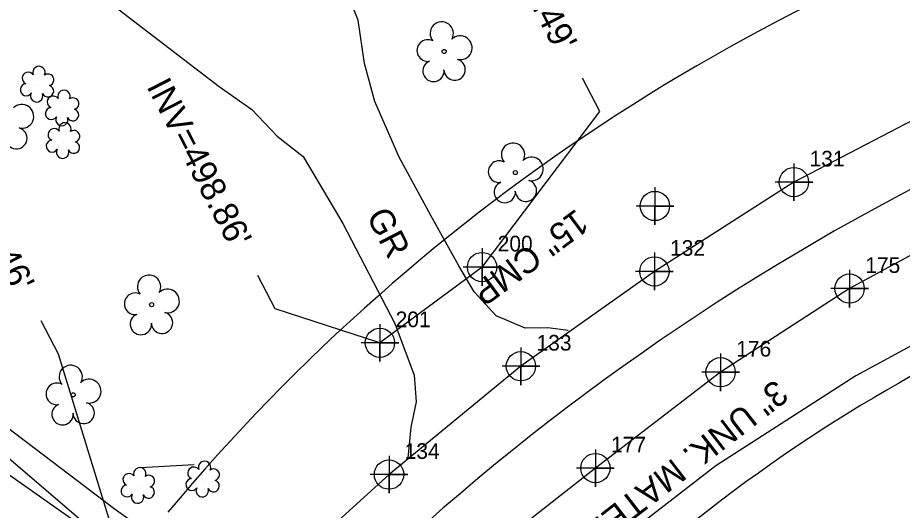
# Model space of a CAD drawing. Extents: x 1534145 to 1537876, y 509021 to 513201.
# Drawn here: x 1536471.7 to 1536612.8, y 511366.8 to 511445.5 of the extents above; entities that cross this region are included whole.
import ezdxf

# ---------------------------------------------------------------- set-up
doc = ezdxf.new("R2010")
doc.units = 0
for name, color, linetype in [('Default Symbol CELL', 7, 'Continuous'), ('Exist Horizontal Alignment', 7, 'Continuous'), ('Exist Other Culture Billboard Cableway', 7, 'Continuous'), ('Exist Right of Way Line', 7, 'Continuous'), ('Exist Roads EOP', 7, 'Continuous'), ('Exist Roads EOP Cogo Number', 7, 'Continuous'), ('Exist Roads EOP Cogo Point CELL', 7, 'Continuous'), ('Exist Roads Soil', 7, 'Continuous'), ('Exist Roads Soil Text', 7, 'Continuous'), ('Exist Structure Minor Pipes CMP 15 Inch', 7, 'Continuous'), ('Exist Structure Minor Pipes CMP 15 Inch Cogo Number', 7, 'Continuous'), ('Exist Structure Minor Pipes CMP 15 Inch Cogo Point CELL', 7, 'Continuous'), ('Exist Structure Minor Pipes CMP 15 Inch Invert', 7, 'Continuous'), ('Exist Structure Minor Pipes CMP 15 Inch Text', 7, 'Continuous'), ('Exist Structure Minor Pipes CMP 18 Inch Invert', 7, 'Continuous'), ('Exist Utilities Telephone UG FO SUE', 7, 'Continuous'), ('Exist Utilities TV UG Cable', 7, 'Continuous'), ('Exist Utilities Water UG Line SUE', 7, 'Continuous'), ('Exist Utilities Water UG Line SUE Text', 7, 'Continuous'), ('Exist Vegetation Shrub CELL', 7, 'Continuous'), ('Exist Vegetation Tree CELL', 7, 'Continuous')]:
    doc.layers.add(name, color=color, linetype=linetype)

msp = doc.modelspace()

# ---------------------------------------------------------------- linework, layer by layer
at = {"layer": 'Default Symbol CELL'}
msp.add_lwpolyline([(1536573.37, 511418.41), (1536573.37, 511412.41), (1536573.37, 511415.41), (1536576.37, 511415.41), (1536570.37, 511415.41)], dxfattribs=at)
msp.add_circle((1536573.37, 511415.41), 2.34, dxfattribs=at)
at = {"layer": 'Exist Horizontal Alignment'}
msp.add_arc((1536795.22, 511072.63), 390, 105.6865, 140.1365, dxfattribs=at)
at = {"layer": 'Exist Other Culture Billboard Cableway'}
msp.add_lwpolyline([(1536491.3, 511373.67), (1536499.85, 511374.11)], dxfattribs=at)
at = {"layer": 'Exist Right of Way Line'}
msp.add_lwpolyline([(1536145.81, 511737.79), (1536209.6, 511636.11), (1536268.44, 511561.44), (1536375.73, 511456.33), (1536489.24, 511358.86)], dxfattribs=at)
for radius in [319.6, 259.6]:
    msp.add_arc((1536740.96, 511161.67), radius, 105.6865, 140.1365, dxfattribs=at)
at = {"layer": 'Exist Roads EOP'}
for points in [[(1536631.58, 511437.38), (1536631.26, 511437.24), (1536618.41, 511431.15), (1536595.54, 511419.22), (1536573.28, 511404.96), (1536551.98, 511389.82), (1536530.94, 511372.53), (1536511.9, 511355.24), (1536502.63, 511347.19), (1536496.64, 511344.02), (1536490.92, 511343.71), (1536482.45, 511344.56), (1536475.44, 511348.14), (1536453.49, 511366.6), (1536410.8, 511403.51), (1536369.08, 511439.8), (1536328.72, 511476.49)], [(1536643.71, 511422.19), (1536639.39, 511420.35), (1536626.28, 511414.11), (1536604.43, 511402.22), (1536583.84, 511388.86), (1536563.87, 511373.55), (1536543.15, 511357.26), (1536525.59, 511342.05), (1536518.95, 511333.47), (1536516.92, 511324.68), (1536516.34, 511315.32), (1536522.83, 511308.58), (1536535.62, 511298.19), (1536578.33, 511263.58), (1536620.78, 511229.16), (1536664.52, 511193.98), (1536707, 511159.44), (1536743.27, 511128.84)]]:
    msp.add_lwpolyline(points, dxfattribs=at)
at = {"layer": 'Exist Roads EOP Cogo Point CELL'}
for points in [[(1536595.54, 511422.22), (1536595.54, 511416.22), (1536595.54, 511419.22), (1536598.54, 511419.22), (1536592.54, 511419.22)], [(1536573.28, 511407.96), (1536573.28, 511401.96), (1536573.28, 511404.96), (1536576.28, 511404.96), (1536570.28, 511404.96)], [(1536604.43, 511405.22), (1536604.43, 511399.22), (1536604.43, 511402.22), (1536607.43, 511402.22), (1536601.43, 511402.22)], [(1536551.98, 511392.82), (1536551.98, 511386.82), (1536551.98, 511389.82), (1536554.98, 511389.82), (1536548.98, 511389.82)], [(1536583.84, 511391.86), (1536583.84, 511385.86), (1536583.84, 511388.86), (1536586.84, 511388.86), (1536580.84, 511388.86)], [(1536563.87, 511376.55), (1536563.87, 511370.55), (1536563.87, 511373.55), (1536566.87, 511373.55), (1536560.87, 511373.55)], [(1536530.94, 511375.53), (1536530.94, 511369.53), (1536530.94, 511372.53), (1536533.94, 511372.53), (1536527.94, 511372.53)]]:
    msp.add_lwpolyline(points, dxfattribs=at)
for centre in [(1536595.54, 511419.22), (1536573.28, 511404.96), (1536604.43, 511402.22), (1536551.98, 511389.82), (1536583.84, 511388.86), (1536563.87, 511373.55), (1536530.94, 511372.53)]:
    msp.add_circle(centre, 2.34, dxfattribs=at)
at = {"layer": 'Exist Roads Soil'}
for points in [[(1536559.52, 511395.55), (1536556.28, 511395.95), (1536552.65, 511395.88), (1536548.04, 511397.86), (1536544.5, 511401.73), (1536542.08, 511405.87), (1536537.59, 511413.88), (1536532.56, 511423.21), (1536528.7, 511432.08), (1536527.05, 511438.17), (1536526.04, 511445.06), (1536516.68, 511468.36), (1536514.31, 511473.66)], [(1536479.05, 511454.45), (1536484.68, 511449.25), (1536503.86, 511434.49), (1536509.05, 511430.81), (1536513.11, 511426.58), (1536517.23, 511423.29), (1536523.59, 511412.59), (1536531.84, 511396.62), (1536534.97, 511388.37), (1536535.29, 511384.16)], [(1536535.29, 511384.16), (1536534.4, 511380.09)], [(1536534.4, 511380.09), (1536533.96, 511375.13)]]:
    msp.add_lwpolyline(points, dxfattribs=at)
at = {"layer": 'Exist Structure Minor Pipes CMP 15 Inch'}
msp.add_line((1536545.78, 511405.66), (1536529.49, 511393.56), dxfattribs=at)
at = {"layer": 'Exist Structure Minor Pipes CMP 15 Inch Cogo Point CELL'}
for points in [[(1536545.78, 511408.66), (1536545.78, 511402.66), (1536545.78, 511405.66), (1536548.78, 511405.66), (1536542.78, 511405.66)], [(1536529.49, 511396.56), (1536529.49, 511390.56), (1536529.49, 511393.56), (1536532.49, 511393.56), (1536526.49, 511393.56)]]:
    msp.add_lwpolyline(points, dxfattribs=at)
for centre in [(1536545.78, 511405.66), (1536529.49, 511393.56)]:
    msp.add_circle(centre, 2.34, dxfattribs=at)
at = {"layer": 'Exist Structure Minor Pipes CMP 15 Inch Invert'}
for points in [[(1536545.78, 511405.66), (1536564.56, 511430.51), (1536561.81, 511435.84)], [(1536529.49, 511393.56), (1536512.76, 511398.98), (1536510.01, 511404.31)]]:
    msp.add_lwpolyline(points, dxfattribs=at)
at = {"layer": 'Exist Structure Minor Pipes CMP 18 Inch Invert'}
msp.add_lwpolyline([(1536489.17, 511356.02), (1536478.18, 511391.73), (1536475.42, 511397.07)], dxfattribs=at)
at = {"layer": 'Exist Utilities Telephone UG FO SUE'}
for p, q in [((1536461.86, 511386.19), (1536487.09, 511367.1)), ((1536487.09, 511367.1), (1536505.96, 511353.75))]:
    msp.add_line(p, q, dxfattribs=at)
at = {"layer": 'Exist Utilities TV UG Cable'}
msp.add_line((1536457.6, 511381.47), (1536483.03, 511363.56), dxfattribs=at)
at = {"layer": 'Exist Utilities Water UG Line SUE'}
for p, q in [((1536626.76, 511399.92), (1536605.41, 511388.3)), ((1536605.41, 511388.3), (1536583.08, 511373.94)), ((1536583.08, 511373.94), (1536564.85, 511359.84))]:
    msp.add_line(p, q, dxfattribs=at)
at = {"layer": 'Exist Vegetation Shrub CELL'}
for p, q in [((1536474.86, 511434.69), (1536474.86, 511434.69)), ((1536478.86, 511430.88), (1536478.86, 511430.88)), ((1536479, 511425.68), (1536479, 511425.68)), ((1536490.94, 511370.61), (1536490.94, 511370.61)), ((1536501.28, 511371.63), (1536501.28, 511371.63))]:
    msp.add_line(p, q, dxfattribs=at)
for centre, radius, start, end in [((1536473.38, 511435.81), 0.968, 35.8908, 245.4216), ((1536475.09, 511436.73), 0.99, 334.8391, 200.4717), ((1536476.53, 511435.56), 0.929, 284.4567, 126.0861), ((1536473.06, 511433.98), 0.955, 95.1099, 327.9534), ((1536476.5, 511433.76), 0.937, 204.9913, 73.4601), ((1536479.08, 511432.92), 0.99, 334.8391, 200.4717), ((1536474.73, 511433), 0.984, 151.2797, 21.387), ((1536477.37, 511432), 0.968, 35.8908, 245.4216), ((1536480.53, 511431.75), 0.929, 284.4567, 126.0861), ((1536477.06, 511430.17), 0.955, 95.1099, 327.9534), ((1536478.73, 511429.19), 0.984, 151.2797, 21.387), ((1536480.49, 511429.95), 0.937, 204.9913, 73.4601), ((1536479.23, 511427.72), 0.99, 334.8391, 200.4717), ((1536477.52, 511426.81), 0.968, 35.8908, 245.4216), ((1536480.67, 511426.55), 0.929, 284.4567, 126.0861), ((1536477.2, 511424.98), 0.955, 95.1099, 327.9534), ((1536480.64, 511424.75), 0.937, 204.9913, 73.4601), ((1536478.87, 511424), 0.984, 151.2797, 21.387), ((1536501.51, 511373.67), 0.99, 334.8391, 200.4717), ((1536491.17, 511372.65), 0.99, 334.8391, 200.4717), ((1536499.8, 511372.75), 0.968, 35.8908, 245.4216), ((1536502.95, 511372.5), 0.929, 284.4567, 126.0861), ((1536489.45, 511371.73), 0.968, 35.8908, 245.4216), ((1536492.61, 511371.48), 0.929, 284.4567, 126.0861), ((1536499.48, 511370.92), 0.955, 95.1099, 327.9534), ((1536489.14, 511369.9), 0.955, 95.1099, 327.9534), ((1536492.57, 511369.68), 0.937, 204.9913, 73.4601), ((1536501.15, 511369.94), 0.984, 151.2797, 21.387), ((1536502.92, 511370.7), 0.937, 204.9913, 73.4601), ((1536490.81, 511368.92), 0.984, 151.2797, 21.387)]:
    msp.add_arc(centre, radius, start, end, dxfattribs=at)
at = {"layer": 'Exist Vegetation Tree CELL'}
for p, q in [((1536539.74, 511440.09), (1536539.74, 511440.09)), ((1536551.11, 511420.74), (1536551.11, 511420.74)), ((1536493.05, 511399.65), (1536493.05, 511399.65)), ((1536480.54, 511385.25), (1536480.54, 511385.25))]:
    msp.add_line(p, q, dxfattribs=at)
for centre in [(1536539.74, 511440.09), (1536551.11, 511420.74), (1536493.05, 511399.65), (1536480.54, 511385.25)]:
    msp.add_circle(centre, 0.326, dxfattribs=at)
for centre, radius, start, end in [((1536539.35, 511442.96), 1.86, 330.1651, 219.7134), ((1536542.29, 511440.68), 1.9, 257.1011, 134.1999), ((1536537.13, 511440.24), 1.73, 62.6636, 279.3457), ((1536538.03, 511436.97), 1.69, 111.5671, 6.231), ((1536541.41, 511437.19), 1.7, 181.2822, 74.56), ((1536472.35, 511429.72), 1.9, 257.1011, 134.1999), ((1536471.48, 511426.23), 1.7, 181.2822, 74.56), ((1536550.73, 511423.61), 1.86, 330.1651, 219.7134), ((1536548.51, 511420.89), 1.73, 62.6636, 279.3457), ((1536553.66, 511421.33), 1.9, 257.1011, 134.1999), ((1536549.41, 511417.62), 1.69, 111.5671, 6.231), ((1536552.79, 511417.84), 1.7, 181.2822, 74.56), ((1536492.66, 511402.52), 1.86, 330.1651, 219.7134), ((1536490.44, 511399.8), 1.73, 62.6636, 279.3457), ((1536495.59, 511400.24), 1.9, 257.1011, 134.1999), ((1536491.34, 511396.53), 1.69, 111.5671, 6.231), ((1536494.72, 511396.75), 1.7, 181.2822, 74.56), ((1536480.16, 511388.12), 1.86, 330.1651, 219.7134), ((1536483.09, 511385.84), 1.9, 257.1011, 134.1999), ((1536477.94, 511385.4), 1.73, 62.6636, 279.3457), ((1536478.84, 511382.13), 1.69, 111.5671, 6.231), ((1536482.22, 511382.35), 1.7, 181.2822, 74.56)]:
    msp.add_arc(centre, radius, start, end, dxfattribs=at)

# ---------------------------------------------------------------- texts
at = {"layer": 'Exist Roads EOP Cogo Number'}
for s, p in [('131', (1536598.04, 511421.72)), ('132', (1536575.78, 511407.46)), ('175', (1536606.93, 511404.72)), ('133', (1536554.48, 511392.32)), ('176', (1536586.34, 511391.36)), ('134', (1536533.44, 511375.03)), ('177', (1536566.37, 511376.05))]:
    msp.add_text(s, height=2.5, dxfattribs=at).set_placement(p)
at = {"layer": 'Exist Roads Soil Text'}
msp.add_text('GR', height=4, rotation=297.3036, dxfattribs=at).set_placement((1536527.25, 511413.83))
at = {"layer": 'Exist Structure Minor Pipes CMP 15 Inch Cogo Number'}
for s, p in [('200', (1536548.28, 511408.16)), ('201', (1536531.99, 511396.06))]:
    msp.add_text(s, height=2.5, dxfattribs=at).set_placement(p)
at = {"layer": 'Exist Structure Minor Pipes CMP 15 Inch Invert'}
for s, p in [("INV=498.49'", (1536544.08, 511465.87)), ("INV=498.86'", (1536492.18, 511434.51))]:
    msp.add_text(s, height=4, rotation=297.2825, dxfattribs=at).set_placement(p)
at = {"layer": 'Exist Structure Minor Pipes CMP 15 Inch Text'}
msp.add_text('15" CMP', height=4, rotation=216.6149, dxfattribs=at).set_placement((1536560.83, 511415.1))
at = {"layer": 'Exist Structure Minor Pipes CMP 18 Inch Invert'}
msp.add_text("INV=496.46'", height=4, rotation=297.2825, dxfattribs=at).set_placement((1536457.51, 511427.43))
at = {"layer": 'Exist Utilities Water UG Line SUE Text'}
msp.add_text('3" UNK. MATERIAL', height=4, rotation=217.7171, dxfattribs=at).set_placement((1536592.59, 511387.87))

doc.saveas('drawing.dxf')
